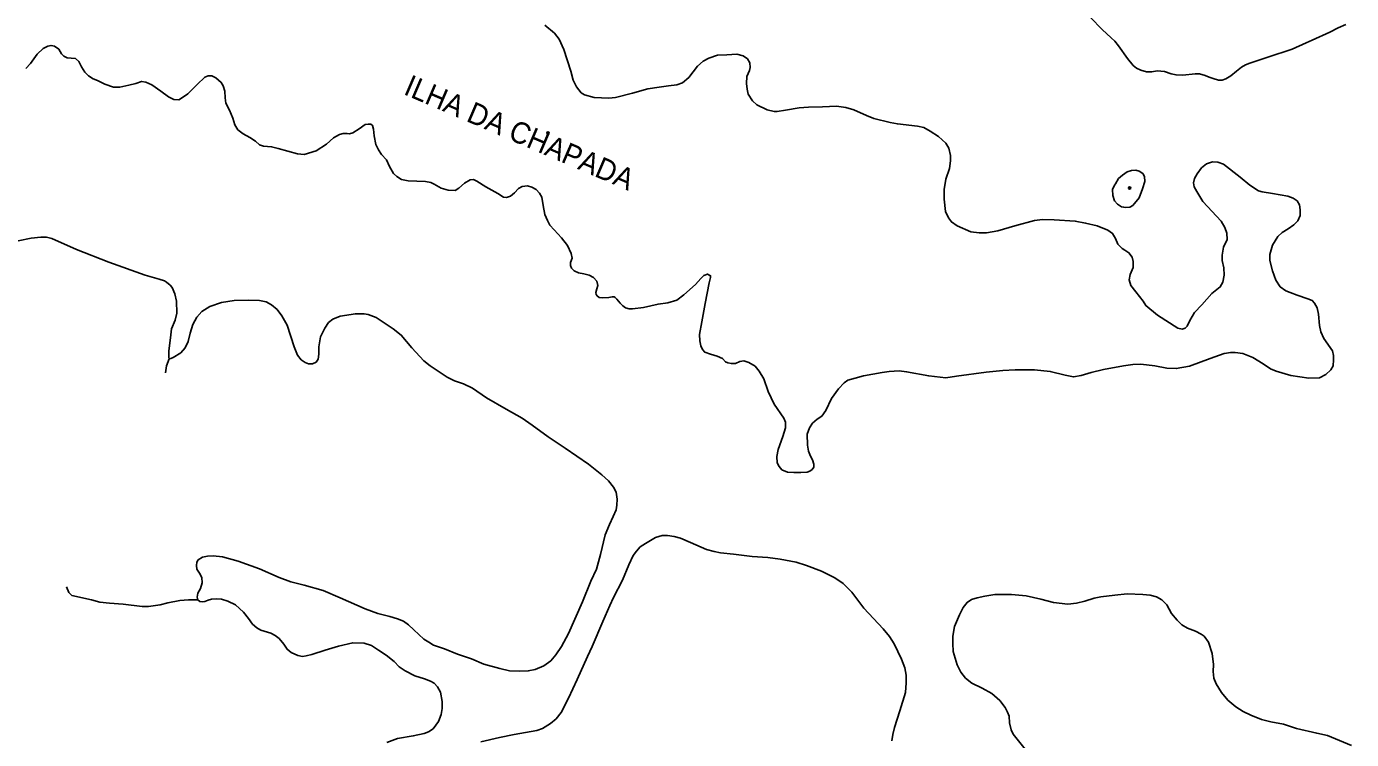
# Model space of a CAD drawing. Extents: x 396 to 422.2, y 7649.8 to 7677.6.
# Drawn here: x 407.27 to 415.91, y 7668.32 to 7672.97 of the extents above; entities that cross this region are included whole.
import ezdxf
from ezdxf.enums import TextEntityAlignment as Align

# ---------------------------------------------------------------- set-up
doc = ezdxf.new("R2010")
doc.units = 0
doc.header["$LTSCALE"] = 0.032
doc.header["$PDMODE"] = 32
doc.header["$PDSIZE"] = 0.016
doc.layers.add('2', color=7, linetype='Continuous', lineweight=25)
doc.layers.add('7', color=7, linetype='Continuous', lineweight=25)
doc.layers.add('54', color=7, linetype='Continuous')

msp = doc.modelspace()

# ---------------------------------------------------------------- linework, layer by layer
at = {"layer": '2'}
for points in [[(415.8713, 7672.9831), (415.8222, 7672.9614), (415.7681, 7672.9319), (415.6521, 7672.8798), (415.6139, 7672.8626), (415.5213, 7672.8208), (415.363, 7672.7697), (415.246, 7672.7303), (415.2184, 7672.7195), (415.1909, 7672.7038), (415.1584, 7672.6782), (415.1221, 7672.6468), (415.0896, 7672.6291), (415.066, 7672.6202), (415.0424, 7672.6202), (415.007, 7672.63), (414.981, 7672.6399), (414.9549, 7672.6497), (414.9166, 7672.6615), (414.89, 7672.6615), (414.8084, 7672.6517), (414.7651, 7672.6536), (414.7327, 7672.6615), (414.6884, 7672.6753), (414.6422, 7672.6802), (414.6068, 7672.6733), (414.5714, 7672.6743), (414.535, 7672.6841), (414.5065, 7672.6979), (414.4859, 7672.7146), (414.4475, 7672.7618), (414.3905, 7672.8434), (414.3649, 7672.8739), (414.3423, 7672.8965), (414.2833, 7672.9506), (414.2076, 7673.0283)], [(411.6815, 7672.7423), (411.6451, 7672.71), (411.5873, 7672.6374), (411.547, 7672.6024), (411.5107, 7672.589), (411.4555, 7672.5823), (411.3937, 7672.5742), (411.3197, 7672.5634), (411.2202, 7672.5352), (411.11, 7672.507), (411.0669, 7672.5016), (410.9701, 7672.507), (410.9083, 7672.5231), (410.8867, 7672.5365), (410.8545, 7672.5755), (410.833, 7672.6199), (410.8195, 7672.6791), (410.7724, 7672.8189), (410.7415, 7672.8862), (410.7119, 7672.9265), (410.6487, 7672.9776)], [(407.2655, 7672.6952), (407.2951, 7672.7288), (407.3381, 7672.788), (407.3771, 7672.827), (407.4094, 7672.8418), (407.4296, 7672.8458), (407.4511, 7672.8418), (407.4793, 7672.8216), (407.4968, 7672.792), (407.5129, 7672.7759), (407.5344, 7672.7651), (407.56, 7672.7638), (407.5882, 7672.7598), (407.6097, 7672.7409), (407.6286, 7672.706), (407.6501, 7672.6724), (407.6729, 7672.6468), (407.7039, 7672.6293), (407.7335, 7672.6172), (407.7805, 7672.593), (407.837, 7672.5742), (407.8773, 7672.5729), (407.9365, 7672.5863), (407.9822, 7672.5984), (408.0199, 7672.6119), (408.0481, 7672.6065), (408.0871, 7672.589), (408.1449, 7672.5487), (408.196, 7672.511), (408.231, 7672.4935), (408.2619, 7672.4922), (408.2875, 7672.5056), (408.3224, 7672.5312), (408.3829, 7672.5917), (408.4327, 7672.6387), (408.4542, 7672.6482), (408.4784, 7672.6468), (408.504, 7672.6347), (408.5389, 7672.6051), (408.5524, 7672.5836)], [(411.9423, 7672.7786), (411.902, 7672.788), (411.8361, 7672.7853), (411.7756, 7672.7826), (411.7178, 7672.7625), (411.6815, 7672.7423)], [(414.9302, 7672.0484), (414.9033, 7672.0094), (414.8858, 7671.9785), (414.8791, 7671.9503), (414.8818, 7671.9247), (414.8993, 7671.8938), (414.9396, 7671.8292), (415.058, 7671.7015), (415.0822, 7671.6598), (415.0956, 7671.6222), (415.0983, 7671.5818), (415.0741, 7671.5307), (415.066, 7671.4796), (415.066, 7671.4447), (415.0768, 7671.3963), (415.0795, 7671.3492), (415.0701, 7671.3021), (415.0526, 7671.2725), (414.9988, 7671.2295), (414.9329, 7671.1556), (414.8845, 7671.1045), (414.8536, 7671.052), (414.8374, 7671.0171), (414.824, 7671.0036), (414.8052, 7670.9969), (414.7756, 7671.0023), (414.6438, 7671.087), (414.5685, 7671.1502), (414.5497, 7671.1784), (414.5026, 7671.2389), (414.4703, 7671.2806), (414.4596, 7671.3183), (414.4663, 7671.3519), (414.4851, 7671.3976), (414.4851, 7671.4366), (414.4784, 7671.4662), (414.4569, 7671.4944), (414.4313, 7671.5106), (414.4139, 7671.5227), (414.3856, 7671.5509), (414.3695, 7671.5885), (414.3507, 7671.6208), (414.3197, 7671.6423), (414.2498, 7671.6706), (414.1745, 7671.6881), (414.1073, 7671.7015), (413.9701, 7671.7096), (413.8935, 7671.7123), (413.8424, 7671.7042), (413.7146, 7671.6706), (413.603, 7671.6383), (413.5291, 7671.6249), (413.482, 7671.6235), (413.4269, 7671.6316), (413.3368, 7671.6692), (413.3005, 7671.6961), (413.2803, 7671.7217), (413.2615, 7671.7634), (413.252, 7671.844), (413.2534, 7671.9072), (413.2642, 7671.9745), (413.287, 7672.0444), (413.2951, 7672.0928), (413.2951, 7672.1278), (413.2843, 7672.1762), (413.2642, 7672.2098), (413.2157, 7672.2515), (413.162, 7672.2864), (413.1203, 7672.3106), (413.0786, 7672.3187), (412.9481, 7672.3348), (412.9011, 7672.3443), (412.7949, 7672.3698), (412.7464, 7672.39), (412.6644, 7672.4263), (412.6106, 7672.4411), (412.5501, 7672.4491), (412.46, 7672.4465), (412.3686, 7672.4438), (412.3067, 7672.4384), (412.218, 7672.4236), (412.1642, 7672.4155), (412.144, 7672.4155), (412.0997, 7672.4263), (412.0324, 7672.4586), (412.0028, 7672.4855), (411.9759, 7672.5285), (411.9679, 7672.5608), (411.9638, 7672.5984), (411.9665, 7672.6428), (411.984, 7672.6818), (411.988, 7672.7019), (411.9854, 7672.7315), (411.9706, 7672.7584), (411.9423, 7672.7786)], [(408.5524, 7672.5836), (408.5631, 7672.5473), (408.5645, 7672.5043), (408.5699, 7672.4693), (408.5941, 7672.4249), (408.6156, 7672.3725), (408.6277, 7672.3281), (408.6478, 7672.2959), (408.6828, 7672.269), (408.7258, 7672.2461), (408.7621, 7672.2219), (408.7877, 7672.1977), (408.8146, 7672.1883), (408.867, 7672.1856), (408.9101, 7672.1735), (409.0365, 7672.1385), (409.0808, 7672.1345), (409.1588, 7672.16), (409.2261, 7672.2031), (409.2718, 7672.2434), (409.3094, 7672.2649), (409.3336, 7672.2716), (409.3605, 7672.2716), (409.3753, 7672.2703), (409.3968, 7672.277), (409.4385, 7672.3026), (409.4775, 7672.3295), (409.4963, 7672.3322), (409.5138, 7672.3322), (409.5246, 7672.3241), (409.5326, 7672.3012), (409.5367, 7672.2569), (409.5474, 7672.2004), (409.5649, 7672.1654), (409.5837, 7672.1358), (409.616, 7672.0995), (409.6362, 7672.0565), (409.6631, 7672.0121), (409.6833, 7671.9906), (409.7155, 7671.9731), (409.7586, 7671.9637), (409.815, 7671.961), (409.8715, 7671.9583), (409.9065, 7671.9516), (409.928, 7671.9422), (409.9737, 7671.9166), (410.0181, 7671.9032), (410.0638, 7671.9005), (410.0893, 7671.9153), (410.1243, 7671.9476), (410.162, 7671.9691), (410.1848, 7671.9731), (410.205, 7671.961), (410.2642, 7671.9247), (410.3421, 7671.8817), (410.3798, 7671.8575), (410.3986, 7671.8548), (410.4255, 7671.8629), (410.4511, 7671.8844), (410.4766, 7671.9126), (410.5008, 7671.9261), (410.5371, 7671.9301), (410.564, 7671.922), (410.5923, 7671.9072), (410.6138, 7671.883), (410.6286, 7671.8575), (410.6393, 7671.8037), (410.6487, 7671.7432), (410.6662, 7671.7042), (410.681, 7671.6746), (410.7106, 7671.645), (410.7577, 7671.5912), (410.7967, 7671.5428), (410.8209, 7671.489), (410.8276, 7671.4595), (410.8168, 7671.4312), (410.8168, 7671.411), (410.8222, 7671.3949), (410.8397, 7671.3761), (410.8679, 7671.364), (410.9029, 7671.3573), (410.9392, 7671.3492), (410.9674, 7671.3331), (410.9889, 7671.3089), (410.9957, 7671.282), (410.9876, 7671.2604), (410.9822, 7671.2362), (410.9836, 7671.2228), (410.9903, 7671.2134), (411.0024, 7671.204), (411.0279, 7671.1999), (411.0656, 7671.2026), (411.0871, 7671.2067), (411.1006, 7671.2067), (411.1086, 7671.204)], [(415.183, 7671.9879), (415.0741, 7672.0713), (415.0364, 7672.0847), (415.0015, 7672.0874), (414.9638, 7672.074), (414.9302, 7672.0484)], [(412.378, 7670.0704), (412.3914, 7670.0825), (412.4036, 7670.0973), (412.4036, 7670.1175), (412.3941, 7670.1444), (412.382, 7670.1686), (412.3672, 7670.2022), (412.3619, 7670.2398), (412.3605, 7670.3124), (412.374, 7670.3541), (412.3941, 7670.3837), (412.4237, 7670.4093), (412.4546, 7670.4294), (412.4802, 7670.4657), (412.5192, 7670.5451), (412.5649, 7670.6069), (412.5999, 7670.6473), (412.6254, 7670.6634), (412.6725, 7670.6782), (412.7276, 7670.6916), (412.8486, 7670.7145), (412.8944, 7670.7199), (412.9603, 7670.7253), (413.0073, 7670.7185), (413.1525, 7670.6916), (413.2628, 7670.6795), (413.3327, 7670.6903), (413.5277, 7670.7158), (413.6353, 7670.7266), (413.716, 7670.7306), (413.841, 7670.732), (413.9446, 7670.7212), (414.0414, 7670.697), (414.0965, 7670.6849), (414.1463, 7670.6943), (414.2122, 7670.7132), (414.2915, 7670.7333), (414.4219, 7670.7575), (414.4824, 7670.7669), (414.5349, 7670.7683), (414.6263, 7670.7575), (414.7057, 7670.7427), (414.7662, 7670.7401), (414.8522, 7670.7562), (414.9867, 7670.8046), (415.0781, 7670.8369), (415.1212, 7670.8449), (415.1494, 7670.8449), (415.1992, 7670.8369), (415.265, 7670.8127), (415.3336, 7670.7696), (415.3807, 7670.7387), (415.4183, 7670.7226), (415.5138, 7670.6943), (415.6295, 7670.6768), (415.7007, 7670.6795), (415.7411, 7670.7011), (415.7747, 7670.7306), (415.7881, 7670.7575), (415.7922, 7670.7965), (415.7922, 7670.8248), (415.7841, 7670.8557), (415.729, 7670.935), (415.7088, 7670.9794), (415.6994, 7671.0211), (415.694, 7671.095), (415.6859, 7671.1367), (415.6684, 7671.165), (415.6523, 7671.1838), (415.6241, 7671.1946), (415.5541, 7671.2188), (415.5084, 7671.2349), (415.4815, 7671.247), (415.4439, 7671.2725), (415.4143, 7671.3156), (415.3928, 7671.3761), (415.3767, 7671.4433), (415.3753, 7671.4823), (415.3928, 7671.5442), (415.4291, 7671.6006), (415.4573, 7671.6275), (415.495, 7671.6504), (415.5326, 7671.676), (415.5582, 7671.7028), (415.573, 7671.7378), (415.5743, 7671.7741), (415.5689, 7671.8064), (415.5541, 7671.8333), (415.5286, 7671.8494), (415.4936, 7671.8642), (415.3928, 7671.8803), (415.3256, 7671.8911), (415.3013, 7671.8978), (415.2462, 7671.9341), (415.183, 7671.9879)], [(414.3691, 7671.9444), (414.3898, 7671.9785), (414.4156, 7672.0013), (414.4456, 7672.022), (414.4746, 7672.0313), (414.5015, 7672.0323), (414.5253, 7672.0271), (414.548, 7672.0116), (414.5594, 7671.9909), (414.5615, 7671.9589), (414.546, 7671.9113), (414.5253, 7671.8534)], [(414.5253, 7671.8534), (414.4839, 7671.8027), (414.4632, 7671.7923), (414.4373, 7671.7903), (414.4239, 7671.7913), (414.4084, 7671.7944), (414.3825, 7671.812), (414.3639, 7671.8337), (414.3515, 7671.8668), (414.3505, 7671.9072), (414.3629, 7671.9351), (414.3691, 7671.9444)], [(408.1987, 7670.8041), (408.1967, 7670.8119), (408.1977, 7670.8522), (408.2095, 7670.9604), (408.2154, 7670.9988), (408.238, 7671.0548), (408.2488, 7671.101), (408.2478, 7671.1797), (408.237, 7671.2259), (408.2193, 7671.2672), (408.2065, 7671.2829), (408.1829, 7671.3036), (408.1702, 7671.3114), (408.1348, 7671.3223), (408.0423, 7671.3488), (407.8073, 7671.4324), (407.5959, 7671.515), (407.4346, 7671.5868), (407.3993, 7671.5956), (407.3619, 7671.5956), (407.2999, 7671.5897), (407.2154, 7671.573)], [(411.1987, 7671.13), (411.2216, 7671.1287), (411.2915, 7671.1381), (411.387, 7671.1596), (411.4515, 7671.1677), (411.5093, 7671.1865), (411.5564, 7671.2201), (411.6304, 7671.2887), (411.6653, 7671.3263), (411.6868, 7671.3465), (411.7097, 7671.3559), (411.7299, 7671.3452), (411.7299, 7671.3331), (411.7205, 7671.2994), (411.6936, 7671.1636), (411.672, 7671.0439), (411.6573, 7670.9619), (411.6599, 7670.9202), (411.6667, 7670.888), (411.6774, 7670.8638), (411.6922, 7670.8476), (411.7299, 7670.8328), (411.7729, 7670.8207), (411.8065, 7670.8046), (411.8267, 7670.7844), (411.8415, 7670.7764), (411.8657, 7670.7723), (411.8926, 7670.7737), (411.9208, 7670.7858), (411.9477, 7670.7911), (411.98, 7670.7804), (412.0203, 7670.7562), (412.0472, 7670.7239), (412.0781, 7670.6728), (412.105, 7670.5908), (412.1454, 7670.5074), (412.2072, 7670.4173), (412.2193, 7670.3904), (412.2193, 7670.3541), (412.2005, 7670.2963), (412.1709, 7670.2116), (412.1615, 7670.1659), (412.1642, 7670.1255), (412.1763, 7670.1013), (412.1951, 7670.0798), (412.2314, 7670.065), (412.2731, 7670.0623), (412.3175, 7670.0623), (412.3605, 7670.065), (412.378, 7670.0704)], [(408.8329, 7671.1738), (408.7877, 7671.1826), (408.7149, 7671.1866), (408.6244, 7671.1836), (408.5409, 7671.1708), (408.4651, 7671.1453), (408.413, 7671.1128), (408.3796, 7671.0755), (408.354, 7671.0273), (408.3373, 7670.9702), (408.3245, 7670.9162), (408.3039, 7670.8758), (408.2764, 7670.8434), (408.2262, 7670.8109), (408.2095, 7670.806), (408.1987, 7670.8041)], [(411.1086, 7671.204), (411.1194, 7671.1932), (411.1409, 7671.1663), (411.157, 7671.1488), (411.1759, 7671.1367), (411.1987, 7671.13)], [(408.3875, 7669.232), (408.3825, 7669.2505), (408.3875, 7669.276), (408.4042, 7669.3055), (408.415, 7669.3429), (408.413, 7669.3773), (408.3973, 7669.4058), (408.3806, 7669.4314), (408.3776, 7669.4569), (408.3796, 7669.4776), (408.3884, 7669.4923), (408.416, 7669.51), (408.4494, 7669.5169), (408.4858, 7669.5189), (408.5468, 7669.512), (408.65, 7669.4855), (408.7877, 7669.4353), (408.9165, 7669.3783), (408.9932, 7669.3508), (409.0807, 7669.3272), (409.2046, 7669.2927), (409.3157, 7669.2465), (409.4779, 7669.1747), (409.5596, 7669.1433), (409.6392, 7669.1236), (409.6893, 7669.1089), (409.7267, 7669.0931), (409.7601, 7669.0705), (409.7955, 7669.0361), (409.8604, 7668.9771), (409.8919, 7668.9555), (409.9224, 7668.9378), (409.9952, 7668.9122), (410.0787, 7668.8788), (410.1702, 7668.8483), (410.2518, 7668.8129), (410.356, 7668.7844), (410.418, 7668.7706), (410.4829, 7668.7667), (410.5409, 7668.7696), (410.5871, 7668.7785), (410.6422, 7668.8031), (410.6874, 7668.8355), (410.7198, 7668.8748), (410.7582, 7668.9279), (410.8034, 7669.0135), (410.8939, 7669.219), (410.949, 7669.3537), (410.9853, 7669.4333), (411.0119, 7669.5287), (411.0433, 7669.6566), (411.0699, 7669.7224), (411.0955, 7669.7746), (411.1151, 7669.8188), (411.1181, 7669.8503), (411.121, 7669.8886), (411.1132, 7669.9338), (411.0964, 7669.9663), (411.064, 7670.0076), (411.0207, 7670.0479), (410.9332, 7670.1158), (410.7808, 7670.22), (410.6707, 7670.2947), (410.5655, 7670.3704), (410.5006, 7670.4166), (410.3973, 7670.4756), (410.2685, 7670.5484), (410.178, 7670.6123), (410.119, 7670.6408), (410.0601, 7670.6595), (410.0119, 7670.6841), (409.9017, 7670.7578), (409.8604, 7670.7903), (409.7818, 7670.8739), (409.7129, 7670.9584), (409.6598, 7670.9978), (409.5487, 7671.0735), (409.4976, 7671.0932), (409.472, 7671.0971), (409.414, 7671.0971), (409.3157, 7671.0804), (409.2675, 7671.0627), (409.239, 7671.0391), (409.2144, 7671.0037), (409.1869, 7670.9457), (409.1761, 7670.8817), (409.1761, 7670.8336), (409.1712, 7670.8021), (409.1574, 7670.7805), (409.1348, 7670.7716), (409.1072, 7670.7706), (409.0856, 7670.7795), (409.06, 7670.7972), (409.0374, 7670.8267), (409.0148, 7670.8808)], [(409.0148, 7670.8808), (408.9696, 7671.0233), (408.9342, 7671.0833), (408.9037, 7671.1256), (408.8673, 7671.1551), (408.8329, 7671.1738)], [(412.9126, 7668.3134), (412.9185, 7668.3547), (412.9283, 7668.3999), (412.9637, 7668.51), (413.0001, 7668.628), (413.006, 7668.691), (413.004, 7668.7421), (412.9972, 7668.7883), (412.9755, 7668.8453), (412.9273, 7668.9466), (412.8959, 7668.9938), (412.8546, 7669.043), (412.7297, 7669.1787), (412.6501, 7669.2819), (412.595, 7669.338), (412.5409, 7669.3763), (412.4534, 7669.4186), (412.3551, 7669.4569), (412.2872, 7669.4776), (412.183, 7669.4973), (412.1033, 7669.5091), (412.0011, 7669.515), (411.8801, 7669.5297), (411.7946, 7669.5386), (411.7523, 7669.5474), (411.7041, 7669.5612), (411.5989, 7669.6064), (411.534, 7669.6339), (411.4927, 7669.6448), (411.4495, 7669.6507), (411.4131, 7669.6507), (411.3708, 7669.6389), (411.3049, 7669.6005), (411.2715, 7669.5779), (411.2469, 7669.5494), (411.2253, 7669.5218), (411.1977, 7669.4599), (411.1564, 7669.3616), (411.0964, 7669.2485), (411.0728, 7669.1944), (411.0276, 7669.0902), (410.9571, 7668.9283), (410.9283, 7668.8621), (410.8595, 7668.7136), (410.8024, 7668.5916), (410.7552, 7668.4972), (410.7238, 7668.4569), (410.6864, 7668.4274), (410.6343, 7668.394), (410.5959, 7668.3802), (410.4494, 7668.3547), (410.3541, 7668.336), (410.2321, 7668.3065)], [(409.6186, 7668.3035), (409.6893, 7668.3281), (409.7916, 7668.3458), (409.8634, 7668.3606), (409.8909, 7668.3714), (409.9214, 7668.392), (409.9558, 7668.4402), (409.9735, 7668.4845), (409.9794, 7668.5238), (409.9804, 7668.569), (409.9696, 7668.631), (409.9489, 7668.6664), (409.9273, 7668.689), (409.9047, 7668.7028), (409.8654, 7668.7165), (409.8024, 7668.7372), (409.7395, 7668.7706), (409.6992, 7668.7952), (409.6657, 7668.8296), (409.6156, 7668.8709), (409.5655, 7668.9053), (409.5192, 7668.9338), (409.4701, 7668.9496), (409.3963, 7668.9525), (409.3029, 7668.9309), (409.2164, 7668.9053), (409.1299, 7668.8758), (409.0925, 7668.867), (409.0689, 7668.864), (409.0394, 7668.8689), (408.9951, 7668.8896), (408.9686, 7668.9102), (408.947, 7668.9437), (408.9175, 7668.98), (408.8919, 7669.0007), (408.8624, 7669.0145), (408.7965, 7669.0351), (408.7719, 7669.0499), (408.7424, 7669.0744), (408.7159, 7669.1108), (408.6834, 7669.1521), (408.6313, 7669.1993), (408.5822, 7669.2229), (408.5399, 7669.2377), (408.5064, 7669.2396), (408.475, 7669.2377), (408.4543, 7669.2298), (408.4327, 7669.221), (408.416, 7669.22), (408.4002, 7669.2219), (408.3875, 7669.232)], [(414.9765, 7668.9555), (414.948, 7668.9948), (414.9293, 7669.0086), (414.892, 7669.0272), (414.8399, 7669.0479), (414.8025, 7669.0685), (414.772, 7669.099), (414.7356, 7669.1443), (414.7051, 7669.1993), (414.6717, 7669.2318), (414.6363, 7669.2524), (414.596, 7669.2623), (414.5488, 7669.2662), (414.4465, 7669.2711), (414.3659, 7669.2632), (414.2735, 7669.2514), (414.2302, 7669.2426), (414.1702, 7669.2239), (414.1152, 7669.2111), (414.0581, 7669.2042), (413.9667, 7669.2151), (413.8821, 7669.2367), (413.7867, 7669.2583), (413.6914, 7669.2682), (413.5842, 7669.2682), (413.5183, 7669.2564), (413.4682, 7669.2465), (413.4308, 7669.2347), (413.4023, 7669.216), (413.3777, 7669.1826), (413.3521, 7669.1344), (413.3207, 7669.0587), (413.3098, 7668.9958), (413.3098, 7668.9486), (413.3118, 7668.8955), (413.3374, 7668.808), (413.362, 7668.7618), (413.3924, 7668.7214), (413.4337, 7668.69), (413.5016, 7668.6575), (413.5645, 7668.6211), (413.6147, 7668.5769), (413.6501, 7668.5307), (413.6658, 7668.5012), (413.6756, 7668.4737), (413.6796, 7668.4304), (413.6894, 7668.3852), (413.7032, 7668.3576), (413.7808, 7668.2593)], [(415.0267, 7668.6841), (415.0119, 7668.7214), (415.006, 7668.7657), (415.009, 7668.8099), (415.0001, 7668.8827), (414.9765, 7668.9555)], [(415.9087, 7668.2819), (415.7524, 7668.3478), (415.6816, 7668.3625), (415.5508, 7668.394), (415.4662, 7668.4225), (415.3836, 7668.4373), (415.3227, 7668.453), (415.2528, 7668.4796), (415.2027, 7668.5051), (415.1545, 7668.5346), (415.1024, 7668.5789), (415.0621, 7668.628), (415.0267, 7668.6841)]]:
    msp.add_lwpolyline(points, dxfattribs=at)
at = {"layer": '54'}
for p in [(410.6691, 7672.2744), (414.4618, 7671.9163)]:
    msp.add_point(p, dxfattribs=at)
at = {"layer": '7'}
for points in [[(408.1761, 7670.7116), (408.1829, 7670.7578), (408.1987, 7670.8041)], [(407.5299, 7669.3171), (407.5465, 7669.2794), (407.5652, 7669.2598), (407.693, 7669.233), (407.7481, 7669.218), (407.8102, 7669.2098), (407.8998, 7669.2048), (408.0229, 7669.1892), (408.0645, 7669.1882), (408.1411, 7669.2009), (408.191, 7669.2135), (408.2687, 7669.228), (408.325, 7669.2319), (408.3875, 7669.232)]]:
    msp.add_lwpolyline(points, dxfattribs=at)

# ---------------------------------------------------------------- texts
at = {"layer": '54', "width": 0.95}
msp.add_text('ILHA DA CHAPADA', height=0.14, rotation=336.752, dxfattribs=at).set_placement((410.4572, 7672.2143), align=Align.CENTER)

doc.saveas('drawing.dxf')
